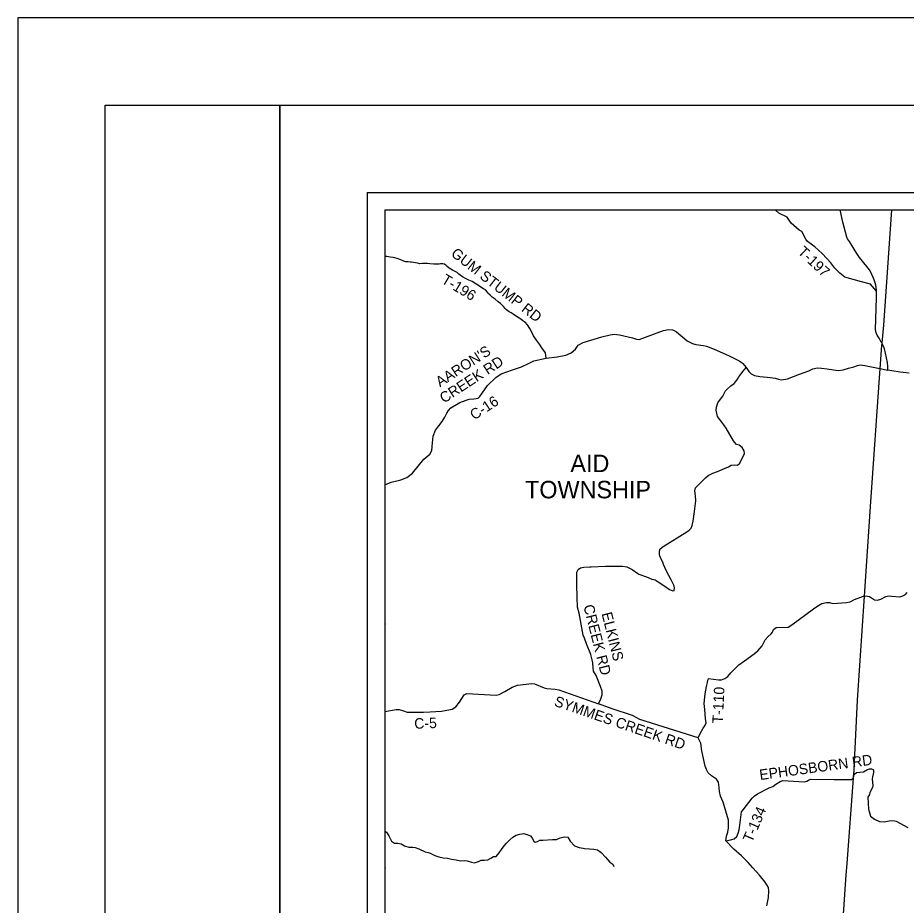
# Model space of a CAD drawing. Extents: x 0 to 34, y 0 to 22.
# Drawn here: x 0 to 5.08, y 16.92 to 22 of the extents above; entities that cross this region are included whole.
import ezdxf

# ---------------------------------------------------------------- set-up
doc = ezdxf.new("R2010")
doc.units = 0
for name, color, linetype in [('GM_X_County_Road', 7, 'Continuous'), ('GM_X_County_Road_Text', 7, 'Continuous'), ('GM_X_State_Route', 7, 'Continuous'), ('GM_X_Township', 7, 'Continuous'), ('GM_X_Township_Road', 7, 'Continuous'), ('GM_X_Township_Road_Text', 7, 'Continuous'), ('GM_X_Township_Text', 7, 'Continuous'), ('SH_Border', 7, 'Continuous'), ('SH_Cut_Line', 7, 'Continuous'), ('SH_Data', 7, 'Continuous')]:
    doc.layers.add(name, color=color, linetype=linetype)

msp = doc.modelspace()

# ---------------------------------------------------------------- linework, layer by layer
at = {"layer": 'GM_X_County_Road'}
for points in [[(2.1, 19.3265), (2.1363, 19.3419), (2.1918, 19.3549), (2.2271, 19.3693), (2.2593, 19.3943), (2.2904, 19.4346), (2.3235, 19.4748), (2.3576, 19.5029), (2.3701, 19.5245), (2.3739, 19.5682), (2.3762, 19.605), (2.3907, 19.6407), (2.4293, 19.6901), (2.4428, 19.7148), (2.455, 19.737), (2.4651, 19.753), (2.4776, 19.7672), (2.5299, 19.799), (2.5656, 19.8123), (2.5826, 19.8176), (2.6097, 19.8201), (2.6229, 19.8204), (2.6346, 19.8237), (2.6441, 19.8319), (2.6869, 19.8962), (2.7351, 19.9417), (2.7659, 19.963), (2.8318, 19.9857), (2.8823, 20.0017), (2.9233, 20.0225), (2.9528, 20.0362), (3.023, 20.053), (3.0859, 20.0589), (3.1352, 20.0699), (3.166, 20.0817), (3.191, 20.1041), (3.2069, 20.1257), (3.2358, 20.1417), (3.3423, 20.1747), (3.3901, 20.1857), (3.4121, 20.1891), (3.4436, 20.186), (3.4675, 20.1807), (3.4929, 20.175), (3.5175, 20.1678), (3.5403, 20.1609), (3.5547, 20.1594), (3.6957, 20.2111), (3.7241, 20.2157), (3.7471, 20.2138), (3.7527, 20.2118), (3.769, 20.2024), (3.8304, 20.1511), (3.8613, 20.1351), (3.8732, 20.1318), (3.875, 20.1313)], [(3.875, 20.1313), (3.8801, 20.1299), (3.9242, 20.124), (3.9405, 20.12), (3.9855, 20.1041), (4.0673, 20.0681), (4.128, 20.0366), (4.1454, 20.0261), (4.1496, 20.0211), (4.1672, 19.9978), (4.184, 19.9763), (4.1966, 19.963), (4.2164, 19.9533), (4.2452, 19.9481), (4.2873, 19.9441), (4.3066, 19.9423), (4.3343, 19.9382), (4.3537, 19.9319), (4.37, 19.9289), (4.4037, 19.9344), (4.4733, 19.9598), (4.5262, 19.9805), (4.55, 19.9905), (4.5762, 19.9967), (4.5981, 19.9957), (4.6315, 19.9902), (4.6672, 19.985), (4.6945, 19.9817), (4.7229, 19.9853), (4.7539, 19.9941), (4.7834, 20.0034), (4.8057, 20.01), (4.8197, 20.0142), (4.8478, 20.0098), (4.9329, 19.9925), (4.9787, 19.9832)], [(3.2812, 18.8577), (3.3639, 18.8622), (3.4595, 18.8624), (3.4853, 18.8572), (3.515, 18.8422), (3.5477, 18.8193), (3.5534, 18.8155), (3.5984, 18.8), (3.6277, 18.7872), (3.6467, 18.7831), (3.6641, 18.7726), (3.6961, 18.7507), (3.7284, 18.7292), (3.7478, 18.7209), (3.7565, 18.7229), (3.7583, 18.7358), (3.7556, 18.7487), (3.7391, 18.7843), (3.7257, 18.8078), (3.7135, 18.8298), (3.702, 18.854), (3.6954, 18.8714), (3.6904, 18.8851), (3.6793, 18.9063), (3.6716, 18.9272), (3.6722, 18.9469), (3.6767, 18.9602), (3.6937, 18.9751), (3.8285, 19.0582), (3.8417, 19.0673), (3.8523, 19.0795), (3.859, 19.094), (3.8645, 19.1202), (3.8715, 19.1754), (3.879, 19.2354), (3.8777, 19.2635), (3.8749, 19.2931), (3.8786, 19.3094), (3.9347, 19.3678), (3.9513, 19.3812), (3.9778, 19.3938), (4.0043, 19.4031), (4.0432, 19.42), (4.0659, 19.4307), (4.0821, 19.4395), (4.1014, 19.4415), (4.1185, 19.4404), (4.1321, 19.4504), (4.1575, 19.5067), (4.1567, 19.5223), (4.1456, 19.5401), (4.127, 19.554), (4.1133, 19.5589), (4.0961, 19.579), (4.0532, 19.6521), (4.0403, 19.6699), (4.0296, 19.6861), (4.0044, 19.7191), (3.9958, 19.7551), (3.9976, 19.7718), (4.005, 19.7969), (4.0201, 19.8179), (4.034, 19.835), (4.043, 19.8529), (4.0501, 19.8651), (4.0588, 19.8754), (4.0807, 19.8937), (4.0992, 19.9079), (4.109, 19.9182), (4.1176, 19.9311), (4.1255, 19.946), (4.1424, 19.9677), (4.1672, 19.9978)], [(2.476, 18.0418), (2.4862, 18.0436), (2.5073, 18.0574), (2.5276, 18.0844), (2.5536, 18.1256), (2.5691, 18.134), (2.7375, 18.1239), (2.7553, 18.1267), (2.7878, 18.144), (2.829, 18.1689), (2.8596, 18.1804), (2.9422, 18.1904), (2.957, 18.1889), (3.0117, 18.1657), (3.0281, 18.1624), (3.0743, 18.1577), (3.0956, 18.1537), (3.3235, 18.0741), (3.3358, 18.103), (3.3448, 18.1251), (3.3439, 18.1467), (3.3336, 18.174), (3.309, 18.2361), (3.2948, 18.2618), (3.2917, 18.2804), (3.29, 18.3077), (3.2865, 18.3259), (3.2795, 18.3559), (3.2549, 18.4176), (3.2434, 18.449), (3.2357, 18.4672), (3.2275, 18.5089), (3.2115, 18.5927), (3.2037, 18.6268), (3.2015, 18.6852), (3.1996, 18.755), (3.1982, 18.8086), (3.1981, 18.8275), (3.2071, 18.842), (3.2192, 18.8523), (3.2392, 18.8555), (3.2733, 18.8573), (3.2812, 18.8577)], [(4.2862, 16.9173), (4.2952, 16.9655), (4.298, 17.0038), (4.2955, 17.0236), (4.2767, 17.0537), (4.2436, 17.093), (4.2059, 17.1353), (4.1795, 17.1666), (4.1418, 17.204), (4.0976, 17.2418), (4.0509, 17.2907), (4.0552, 17.3172), (4.0638, 17.3397), (4.0663, 17.3647), (4.0672, 17.408), (4.0363, 17.5108), (4.0213, 17.5457), (4.0155, 17.5715), (4.0139, 17.595), (4.0091, 17.6261), (3.9973, 17.6428), (3.9695, 17.6613), (3.9512, 17.6783), (3.9401, 17.6976), (3.9336, 17.7181), (3.9141, 17.8049), (3.9086, 17.8482), (3.8925, 17.88), (3.5603, 17.9852), (3.5168, 18.0065), (3.4017, 18.0457), (3.3235, 18.0741)], [(2.1, 18.0303), (2.1654, 18.041), (2.1768, 18.0408), (2.1817, 18.0407), (2.2068, 18.0333), (2.2273, 18.0262), (2.2664, 18.026), (2.3221, 18.0259), (2.359, 18.0285)], [(2.359, 18.0285), (2.359, 18.0285), (2.4252, 18.033), (2.4755, 18.0417), (2.476, 18.0418)]]:
    msp.add_lwpolyline(points, dxfattribs=at)
at = {"layer": 'GM_X_State_Route'}
msp.add_lwpolyline([(5.101, 19.9666), (5.0495, 19.9712), (5.0018, 19.9787), (4.9787, 19.9832), (4.9791, 20.0049), (4.976, 20.0266), (4.9646, 20.081), (4.9597, 20.1046), (4.9538, 20.1203), (4.9437, 20.1395), (4.9413, 20.144), (4.9284, 20.1674), (4.9169, 20.1842), (4.9117, 20.1976), (4.9082, 20.217), (4.9131, 20.3965), (4.9131, 20.4362), (4.913, 20.4436), (4.9092, 20.4691), (4.9064, 20.4828), (4.9006, 20.4996), (4.8815, 20.5443), (4.8734, 20.5577), (4.8574, 20.5758), (4.8164, 20.6276), (4.8016, 20.6503), (4.759, 20.7188), (4.7482, 20.7357), (4.7434, 20.7453), (4.7215, 20.8295), (4.7055, 20.9)], dxfattribs=at)
at = {"layer": 'GM_X_Township'}
msp.add_lwpolyline([(5.0001, 20.9), (4.9545, 20.2404), (4.9437, 20.1395), (4.9421, 20.1251), (4.9329, 19.9925), (4.8778, 19.2029), (4.8429, 18.6903), (4.8024, 18.0941), (4.7822, 17.662), (4.7809, 17.6483), (4.7438, 17.1604), (4.7383, 17.0951), (4.704, 16.5887)], dxfattribs=at)
at = {"layer": 'GM_X_Township_Road'}
for p, q in [((2.1, 18.5349), (2.1014, 18.5298)), ((2.1063, 17.1312), (2.1, 17.1327))]:
    msp.add_line(p, q, dxfattribs=at)
for points in [[(4.9131, 20.4362), (4.8792, 20.4751), (4.828, 20.4885), (4.7798, 20.5027), (4.7324, 20.5165), (4.704, 20.5378), (4.6748, 20.5675), (4.6529, 20.598), (4.6294, 20.622), (4.6025, 20.6502), (4.5609, 20.6883), (4.5196, 20.7188), (4.5098, 20.734), (4.4856, 20.777), (4.4708, 20.7854), (4.4253, 20.8239), (4.4019, 20.8589), (4.3545, 20.8826), (4.3348, 20.8998), (4.3347, 20.9)], [(3.023, 20.053), (3.0192, 20.0826), (2.9981, 20.1121), (2.9857, 20.1324), (2.9686, 20.1557), (2.9514, 20.1799), (2.9436, 20.1962), (2.9304, 20.2219), (2.9172, 20.2421), (2.9039, 20.2577), (2.8907, 20.2663), (2.879, 20.2744), (2.8479, 20.2951), (2.8343, 20.3036), (2.8226, 20.311), (2.8121, 20.3173), (2.7957, 20.3293), (2.7887, 20.3363), (2.7786, 20.348), (2.7681, 20.3585), (2.7619, 20.3644), (2.7486, 20.3749), (2.7315, 20.3893), (2.7144, 20.4013), (2.7023, 20.4119), (2.6906, 20.4231), (2.6856, 20.4317), (2.6774, 20.4407), (2.6653, 20.4484), (2.6334, 20.4691), (2.6003, 20.4901), (2.5817, 20.4983), (2.5665, 20.5064), (2.5451, 20.5181), (2.524, 20.5337), (2.5139, 20.5419), (2.4995, 20.5493), (2.4878, 20.5551), (2.4684, 20.5672), (2.4579, 20.5761), (2.452, 20.5823), (2.4415, 20.5901), (2.4326, 20.5913), (2.4189, 20.5913), (2.4108, 20.5901), (2.401, 20.5893), (2.3808, 20.5909), (2.3582, 20.5925), (2.3446, 20.5932), (2.3302, 20.594), (2.3162, 20.5932), (2.3002, 20.5928), (2.287, 20.5948), (2.2644, 20.5991), (2.2531, 20.6018), (2.2469, 20.6022), (2.2333, 20.6026), (2.2197, 20.6041), (2.2091, 20.608), (2.1912, 20.615), (2.1702, 20.6224), (2.157, 20.6259), (2.1473, 20.6283), (2.1309, 20.6302), (2.1118, 20.6333), (2.1041, 20.6337), (2.1, 20.6348)], [(4.8629, 18.6906), (4.8734, 18.6887), (4.9018, 18.6689), (4.9185, 18.6666), (4.9394, 18.6726), (4.9675, 18.6874), (4.982, 18.6915), (4.9998, 18.6907), (5.0465, 18.6872), (5.064, 18.6917), (5.0795, 18.7), (5.089, 18.7114)], [(3.9516, 18.2164), (3.9516, 18.2165), (3.9524, 18.2184), (4.0104, 18.2114), (4.0271, 18.2121), (4.0461, 18.2181), (4.0632, 18.2295), (4.08, 18.2511), (4.1085, 18.2807), (4.126, 18.2977), (4.1576, 18.3197), (4.2134, 18.3595), (4.2351, 18.3765), (4.2595, 18.4065), (4.2774, 18.4406), (4.2915, 18.4565), (4.3101, 18.4747), (4.3189, 18.4842), (4.3246, 18.5001), (4.3398, 18.5104), (4.4085, 18.5136), (4.4294, 18.5269), (4.5537, 18.6174), (4.5773, 18.634), (4.6001, 18.6476), (4.6274, 18.654), (4.6453, 18.654), (4.6638, 18.6475), (4.7417, 18.653), (4.7622, 18.6575), (4.7876, 18.6703), (4.8389, 18.6896), (4.8429, 18.6903), (4.8541, 18.6922), (4.8628, 18.6907), (4.8629, 18.6906)], [(3.8925, 17.88), (3.9072, 17.9088), (3.921, 17.935), (3.9312, 17.949), (3.9389, 17.965), (3.9351, 17.9905), (3.9311, 18.041), (3.9285, 18.0767), (3.9336, 18.1314), (3.9409, 18.1732), (3.9459, 18.1964), (3.9486, 18.2089), (3.9516, 18.2164)], [(4.7815, 17.6551), (4.7822, 17.662), (4.7871, 17.671), (4.7994, 17.6818), (4.8182, 17.6829), (4.839, 17.6852), (4.8629, 17.6979), (4.8743, 17.7023), (4.8847, 17.7014), (4.8937, 17.6984), (4.8967, 17.6916), (4.897, 17.6818), (4.8904, 17.6565), (4.8888, 17.6448), (4.8923, 17.605), (4.8904, 17.5949), (4.8754, 17.5666), (4.8733, 17.5554), (4.8646, 17.5398), (4.8679, 17.4717), (4.8784, 17.4318), (4.9027, 17.4131), (4.9303, 17.4001), (4.9569, 17.3989), (4.9869, 17.4049), (5.0078, 17.4068), (5.026, 17.4018), (5.0934, 17.3655)], [(4.0509, 17.2907), (4.0775, 17.2951), (4.0995, 17.3018), (4.114, 17.3147), (4.1214, 17.3334), (4.1279, 17.3528), (4.1309, 17.3802), (4.1403, 17.4561), (4.1498, 17.4675), (4.2024, 17.5334), (4.2142, 17.546), (4.2328, 17.5596), (4.3, 17.5932), (4.3198, 17.6012), (4.3384, 17.614), (4.3631, 17.6303), (4.3776, 17.6352), (4.5001, 17.6281), (4.5157, 17.6322), (4.5252, 17.6375), (4.5362, 17.6424), (4.6697, 17.641), (4.7708, 17.641), (4.7809, 17.6483), (4.7815, 17.6551)], [(2.1, 17.3448), (2.1095, 17.3387), (2.1235, 17.3189), (2.139, 17.2874), (2.1553, 17.2775), (2.1743, 17.2764), (2.1937, 17.2734), (2.2134, 17.2623), (2.2374, 17.2543), (2.2613, 17.2532), (2.2738, 17.2513), (2.2943, 17.2437), (2.3304, 17.2266), (2.349, 17.2232), (2.3596, 17.2186), (2.3858, 17.2068), (2.4097, 17.1992), (2.4337, 17.1927), (2.4587, 17.1908), (2.4811, 17.1855), (2.5085, 17.1805), (2.5335, 17.1748), (2.5567, 17.1771), (2.5719, 17.1756), (2.5954, 17.1672), (2.6133, 17.1634), (2.6361, 17.1714), (2.652, 17.1786), (2.671, 17.1797), (2.6893, 17.182), (2.7075, 17.1903), (2.7216, 17.1998), (2.7379, 17.2013), (2.7554, 17.2207), (2.7679, 17.2412), (2.7832, 17.2606), (2.7972, 17.2776), (2.8155, 17.2966), (2.8333, 17.311), (2.8519, 17.322), (2.8732, 17.3281), (2.8949, 17.3315), (2.9135, 17.3254), (2.9332, 17.3178), (2.9431, 17.3049), (2.9522, 17.2874), (2.9609, 17.2821), (2.9731, 17.2855), (2.9875, 17.2943), (3.0038, 17.2939), (3.0601, 17.2973), (3.0829, 17.298), (3.1038, 17.3075), (3.1265, 17.3128), (3.1478, 17.3101), (3.1607, 17.2885), (3.1861, 17.2623), (3.2127, 17.2528), (3.2351, 17.2478)], [(3.2351, 17.2478), (3.2358, 17.2477), (3.242, 17.2463), (3.2708, 17.244), (3.2966, 17.2425), (3.3179, 17.2379), (3.3373, 17.2227), (3.3627, 17.1957), (3.3874, 17.1688), (3.4052, 17.1562), (3.4108, 17.1424)]]:
    msp.add_lwpolyline(points, dxfattribs=at)
at = {"layer": 'SH_Border'}
for points in [[(0.5, 21.5), (1.5, 21.5), (1.5, 0.5), (0.5, 0.5)], [(1.5, 21.5), (33.5, 21.5), (33.5, 0.5), (1.5, 0.5)]]:
    msp.add_lwpolyline(points, close=True, dxfattribs=at)
at = {"layer": 'SH_Cut_Line'}
msp.add_lwpolyline([(0, 0), (34, 0), (34, 22), (0, 22)], close=True, dxfattribs=at)
at = {"layer": 'SH_Data'}
for p, q in [((2, 21), (9, 21)), ((2, 21), (2, 14)), ((2.1, 20.9), (2.1, 14.1)), ((2.1, 20.9), (8.9, 20.9))]:
    msp.add_line(p, q, dxfattribs=at)

# ---------------------------------------------------------------- texts
at = {"layer": 'GM_X_County_Road_Text'}
for s, rotation, p in [("AARON'S", 33.1008, (2.4159, 19.8845)), ('CREEK RD', 33.1008, (2.4386, 19.7919)), ('C-16', 33.1008, (2.612, 19.6955)), ('CREEK RD', 284.2467, (3.2361, 18.634)), ('ELKINS', 284.2467, (3.3399, 18.5907)), ('SYMMES CREEK RD', 341.1639, (3.0649, 18.0638)), ('C-5', 1.973, (2.2696, 17.9311))]:
    msp.add_text(s, height=0.06, rotation=rotation, dxfattribs=at).set_placement(p)
at = {"layer": 'GM_X_Township_Road_Text'}
for s, rotation, p in [('T-197', 316.4464, (4.4591, 20.6554)), ('GUM STUMP RD', 321.8858, (2.4742, 20.6416)), ('T-196', 328.9197, (2.4193, 20.4858)), ('T-110', 87.104, (4.0336, 17.9605)), ('EPHOSBORN RD', 7.807, (4.2479, 17.6376)), ('T-134', 66.4299, (4.2011, 17.2767))]:
    msp.add_text(s, height=0.06, rotation=rotation, dxfattribs=at).set_placement(p)
at = {"layer": 'GM_X_Township_Text'}
for s, p in [('AID', (3.1623, 19.4)), ('TOWNSHIP', (2.9028, 19.25))]:
    msp.add_text(s, height=0.1, dxfattribs=at).set_placement(p)

doc.saveas('drawing.dxf')
